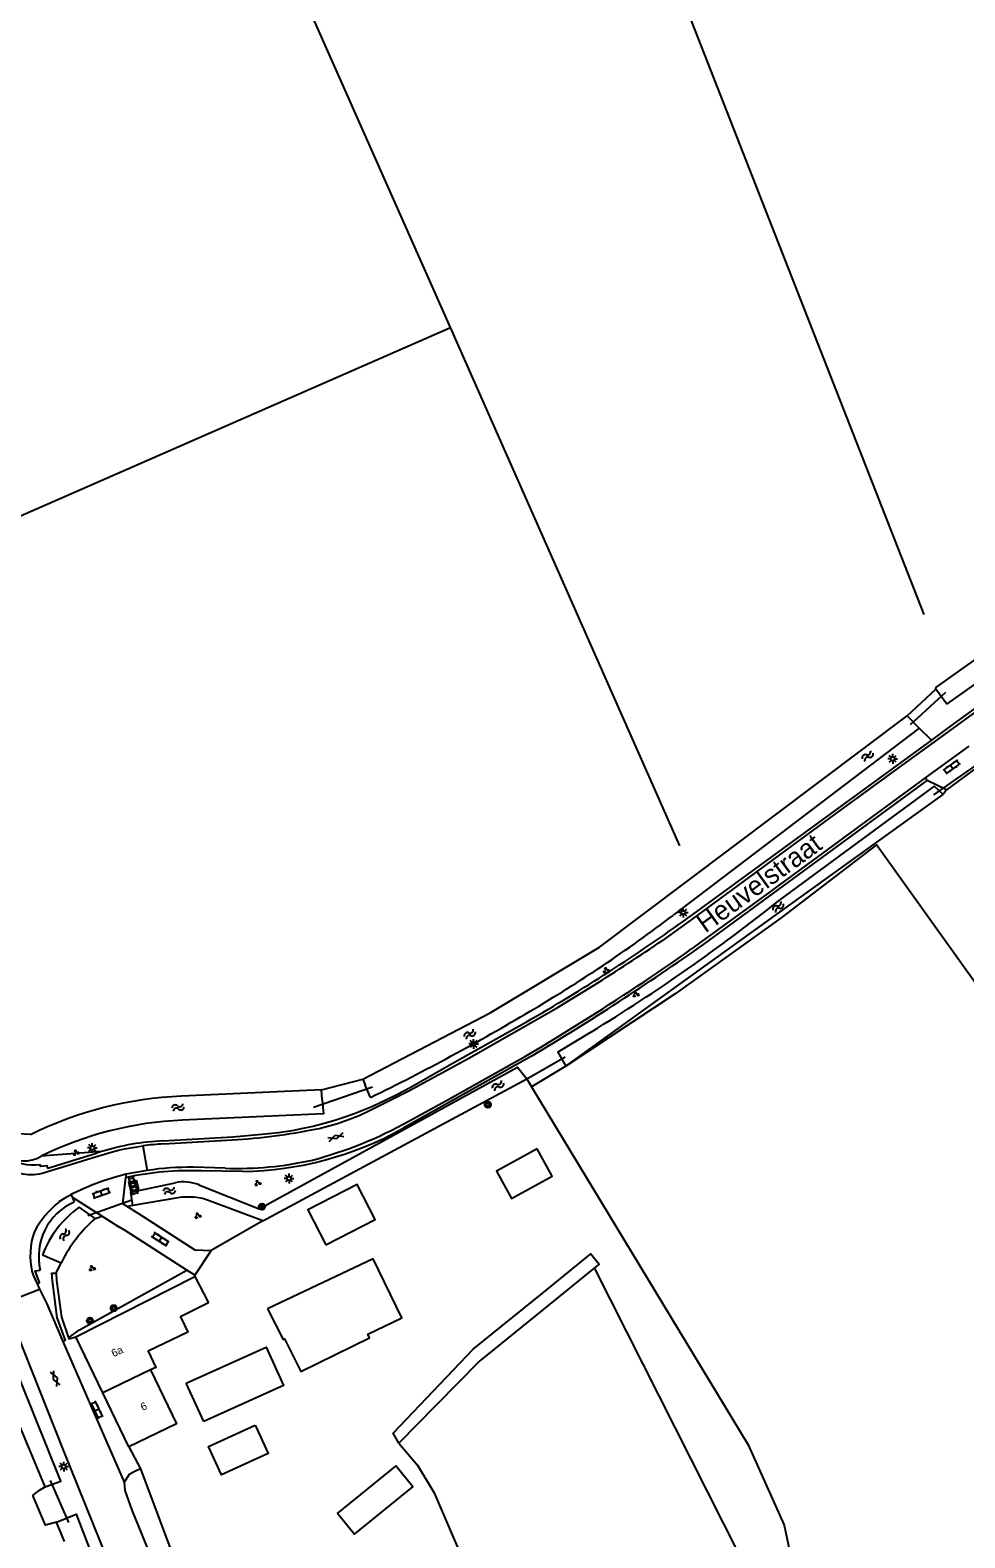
# Model space of a CAD drawing. Extents: x 136000 to 141000, y 400494 to 402006.
# Drawn here: x 137376.4 to 137496.6, y 400727.5 to 400921.3 of the extents above; entities that cross this region are included whole.
import ezdxf

# ---------------------------------------------------------------- set-up
doc = ezdxf.new("R2010")
doc.units = 0
for name, color, linetype in [('gg-afsc-draadraster', 7, 'Continuous'), ('gg-afsc-erfafscheiding', 7, 'Continuous'), ('gg-afsc-lijn draadraster', 7, 'Continuous'), ('gg-anno-huisnummerreeks BGT', 7, 'Continuous'), ('gg-anno-openbare ruimte label', 7, 'Continuous'), ('gg-bbg-bijgebouw', 7, 'Continuous'), ('gg-bbg-gedigitaliseerde bijgebouw', 7, 'Continuous'), ('gg-bbg-hoofdgebouw', 7, 'Continuous'), ('gg-bbg-luifel en loopbrug', 7, 'Continuous'), ('gg-bbg-tussenscheiding', 7, 'Continuous'), ('gg-knt-bronhoudergrens', 7, 'Continuous'), ('gg-knt-verharding', 7, 'Continuous'), ('gg-kntw-bovenkant insteek waterloop', 7, 'Continuous'), ('gg-kntw-midden sloot', 7, 'Continuous'), ('gg-kwrk-duiker nz buis', 7, 'Continuous'), ('gt-grn-groengrens', 7, 'Continuous'), ('gt-symb-boom', 7, 'Continuous'), ('gt-symb-brandkraan', 7, 'Continuous'), ('gt-symb-gesloten verharding', 7, 'Continuous'), ('gt-symb-groenvak', 7, 'Continuous'), ('gt-symb-klinker verharding', 7, 'Continuous'), ('gt-symb-lichtmast', 7, 'Continuous'), ('gt-symb-watersymbool', 7, 'Continuous')]:
    doc.layers.add(name, color=color, linetype=linetype)

# ---------------------------------------------------------------- blocks, each defined once
blk = doc.blocks.new('gt0-WA')
at = {"layer": 'gt-symb-watersymbool'}
for centre, start, end in [((-0.32, 0.02), 28.0725, 151.9275), ((0.43, 0.42), 208.0725, 331.9275), ((-0.32, -0.43), 28.0725, 151.9275), ((0.43, -0.03), 208.0725, 331.9275)]:
    blk.add_arc(centre, 0.425, start, end, dxfattribs=at)
blk = doc.blocks.new('gt0-LMAST')
at = {"layer": 'gt-symb-lichtmast'}
for p, q in [((-0.18, 0.17), (-0.45, 0.44)), ((-0.01, 0.25), (-0.01, 0.62)), ((0.17, 0.17), (0.44, 0.44)), ((-0.26, 0), (-0.63, 0)), ((-0.18, -0.18), (-0.45, -0.45)), ((-0.01, -0.25), (-0.01, -0.63)), ((0.44, -0.45), (0.17, -0.18)), ((0.24, 0), (0.62, 0))]:
    blk.add_line(p, q, dxfattribs=at)
blk.add_circle((-0.01, 0), 0.25, dxfattribs=at)
blk = doc.blocks.new('gt0-KL1')
at = {"layer": 'gt-symb-klinker verharding'}
for p, q in [((-1.15, 0.3), (1.15, 0.3)), ((-1, -0.3), (-1, 0.3)), ((-0.5, 0.3), (-0.5, 0.45)), ((0, -0.3), (0, 0.3)), ((0.5, 0.3), (0.5, 0.45)), ((1, -0.3), (1, 0.3)), ((-1.15, -0.3), (1.15, -0.3)), ((-0.5, -0.45), (-0.5, -0.3)), ((0.5, -0.45), (0.5, -0.3))]:
    blk.add_line(p, q, dxfattribs=at)
blk = doc.blocks.new('gt0-BOOM')
at = {"layer": 'gt-symb-boom'}
for radius in [0.4, 0.2]:
    blk.add_circle((0, 0), radius, dxfattribs=at)
blk = doc.blocks.new('gt0-GRVAK')
at = {"layer": 'gt-symb-groenvak'}
for p, q in [((-0.11, 0.19), (-0.23, 0.24)), ((-0.18, 0.15), (0.09, 0.15)), ((-0.09, 0.21), (-0.16, 0.32)), ((-0.05, 0.21), (-0.05, 0.39)), ((0, 0.21), (0.06, 0.32)), ((0.02, 0.19), (0.13, 0.24)), ((0.26, -0.05), (0.2, 0.06)), ((0.3, -0.05), (0.3, 0.13)), ((0.35, -0.05), (0.41, 0.06)), ((-0.24, -0.23), (-0.36, -0.18)), ((-0.32, -0.26), (-0.05, -0.26)), ((-0.23, -0.21), (-0.29, -0.09)), ((-0.18, -0.2), (-0.18, -0.02)), ((-0.14, -0.21), (-0.07, -0.09)), ((-0.12, -0.23), (0, -0.18)), ((0.24, -0.07), (0.12, -0.02)), ((0.17, -0.11), (0.44, -0.11)), ((0.37, -0.07), (0.49, -0.02))]:
    blk.add_line(p, q, dxfattribs=at)
blk = doc.blocks.new('gt0-BR')
at = {"layer": 'gt-symb-brandkraan'}
for centre, radius, start, end in [((-0.24, 0), 0.206, 107.5669, 252.4331), ((0.6, -2.66), 3, 106.892, 107.5669), ((0, -0.69), 0.938, 73.108, 106.892), ((-0.6, -2.66), 3, 72.4331, 73.108), ((0.24, 0), 0.206, 287.567, 72.4331), ((0.6, 2.66), 3, 252.4331, 253.108), ((0, 0.69), 0.938, 253.108, 286.8921), ((-0.6, 2.66), 3, 286.8921, 287.567)]:
    blk.add_arc(centre, radius, start, end, dxfattribs=at)
blk = doc.blocks.new('gt0-GESVH1')
at = {"layer": 'gt-symb-gesloten verharding'}
for p, q in [((-0.99, -0.26), (0.01, 0.24)), ((0.01, -0.26), (-0.99, 0.24)), ((0.01, 0.24), (1.01, -0.26)), ((1.01, 0.24), (0.01, -0.26))]:
    blk.add_line(p, q, dxfattribs=at)

msp = doc.modelspace()

# ---------------------------------------------------------------- linework, layer by layer
at = {"layer": 'gg-afsc-draadraster'}
msp.add_line((137445.3, 400788.16), (137440.89, 400785.49), dxfattribs=at)
for points in [[(137574.82, 400766.45), (137564.03, 400780.91), (137556.53, 400775.22), (137550.61, 400770.86), (137540.84, 400784.86), (137518.92, 400769.04), (137502.17, 400792.96), (137485.23, 400816.63), (137472.97, 400807.22), (137459.36, 400797.46), (137445.3, 400788.16)], [(137428.37, 400733.35), (137439.78, 400706.75), (137440.85, 400707.2), (137445.39, 400696.61), (137443.56, 400695.83)]]:
    msp.add_lwpolyline(points, dxfattribs=at)
at = {"layer": 'gg-afsc-erfafscheiding'}
for p, q in [((137489.19, 400833.19), (137492.87, 400836.61)), ((137406.34, 400768.29), (137399.71, 400764.48))]:
    msp.add_line(p, q, dxfattribs=at)
msp.add_lwpolyline([(137379.82, 400729.57), (137378.4, 400729.17), (137376.77, 400733), (137377.62, 400733.67), (137378.34, 400734.09)], dxfattribs=at)
at = {"layer": 'gg-afsc-lijn draadraster'}
msp.add_line((137445.3, 400788.16), (137440.89, 400785.49), dxfattribs=at)
msp.add_lwpolyline([(137574.82, 400766.45), (137564.03, 400780.91), (137556.53, 400775.22), (137550.61, 400770.86), (137540.84, 400784.86), (137518.92, 400769.04), (137502.17, 400792.96), (137485.23, 400816.63), (137472.97, 400807.22), (137459.36, 400797.46), (137445.3, 400788.16)], dxfattribs=at)
at = {"layer": 'gg-bbg-bijgebouw'}
msp.add_line((137398.75, 400742.5), (137396.5, 400747.41), dxfattribs=at)
for points in [[(137406.95, 400756.99), (137408.95, 400753.02), (137409.14, 400753.11), (137411.21, 400748.94), (137420.05, 400753.25), (137419.83, 400753.71), (137424.2, 400755.83), (137420.51, 400763.4), (137406.95, 400756.99)], [(137396.5, 400747.41), (137406.75, 400752.05), (137408.98, 400747.13), (137398.75, 400742.5)], [(137405.37, 400742.02), (137407.03, 400738.38), (137401.01, 400735.63), (137399.35, 400739.28), (137405.37, 400742.02)]]:
    msp.add_lwpolyline(points, dxfattribs=at)
at = {"layer": 'gg-bbg-gedigitaliseerde bijgebouw'}
for points in [[(137441.6, 400777.52), (137436.38, 400774.66), (137438.3, 400771.16), (137443.52, 400774.03), (137441.6, 400777.52)], [(137423.43, 400736.8), (137415.93, 400730.72), (137418.13, 400728), (137425.63, 400734.09), (137423.43, 400736.8)]]:
    msp.add_lwpolyline(points, dxfattribs=at)
at = {"layer": 'gg-bbg-hoofdgebouw'}
for p, q in [((137382.3, 400753.4), (137397.62, 400761.14)), ((137397.62, 400761.14), (137399.34, 400757.73)), ((137385.77, 400746.18), (137382.3, 400753.4)), ((137389.11, 400739.25), (137385.77, 400746.18))]:
    msp.add_line(p, q, dxfattribs=at)
for points in [[(137399.34, 400757.73), (137395.76, 400755.95), (137396.7, 400754), (137391.58, 400751.54), (137392.58, 400749.45), (137391.9, 400749.13)], [(137391.9, 400749.13), (137395.24, 400742.2), (137389.11, 400739.25)]]:
    msp.add_lwpolyline(points, dxfattribs=at)
at = {"layer": 'gg-bbg-luifel en loopbrug'}
msp.add_lwpolyline([(137414.45, 400765.19), (137420.78, 400768.45), (137418.46, 400772.95), (137412.13, 400769.7), (137414.45, 400765.19)], dxfattribs=at)
at = {"layer": 'gg-bbg-tussenscheiding'}
msp.add_line((137391.9, 400749.13), (137385.77, 400746.18), dxfattribs=at)
at = {"layer": 'gg-knt-bronhoudergrens'}
for points in [[(137440.89, 400785.49), (137468.72, 400739.5), (137473.35, 400729.18), (137474.96, 400721.64), (137474.68, 400714.1), (137473.24, 400676.77)], [(137468.93, 400678.71), (137469.72, 400721.2), (137449, 400762.23)], [(137423.82, 400739.73), (137426.23, 400736.89), (137428.37, 400733.35)]]:
    msp.add_lwpolyline(points, dxfattribs=at)
at = {"layer": 'gg-knt-verharding'}
for p, q in [((137497.09, 400829.31), (137491.51, 400825.24)), ((137491.76, 400824.89), (137491.51, 400825.24)), ((137498.12, 400826.55), (137494.22, 400823.67)), ((137462.99, 400803.8), (137491.76, 400824.89)), ((137494.22, 400823.67), (137491.76, 400824.89)), ((137440.97, 400789.49), (137424.37, 400780.18)), ((137393.56, 400778.17), (137401.71, 400778.64)), ((137390.92, 400777.93), (137391.45, 400774.75)), ((137391.45, 400774.75), (137388.74, 400774.29)), ((137401.48, 400775.05), (137397.41, 400775.17)), ((137403.76, 400774.63), (137398.49, 400774.71)), ((137388.74, 400774.29), (137387.12, 400773.81)), ((137388.81, 400773.87), (137388.74, 400774.29)), ((137381.68, 400771.65), (137381.86, 400771.25)), ((137381.86, 400771.25), (137382.08, 400770.71)), ((137385.7, 400768.89), (137387.83, 400767.53)), ((137389.58, 400769.72), (137388.92, 400770.13)), ((137399.71, 400764.48), (137397.6, 400761.29)), ((137397.6, 400761.29), (137396.59, 400761.94)), ((137397.6, 400761.29), (137397.62, 400761.14)), ((137373.25, 400757.81), (137377.63, 400759.52)), ((137377.33, 400760.2), (137377.63, 400759.52)), ((137389.11, 400739.25), (137390.61, 400736.41)), ((137389.99, 400736.11), (137389.14, 400735.68)), ((137390.61, 400736.41), (137389.99, 400736.11)), ((137389.14, 400735.68), (137388.52, 400734.69))]:
    msp.add_line(p, q, dxfattribs=at)
for points in [[(137566.7, 400883.53), (137558.63, 400877.45), (137550.43, 400871.48), (137539.55, 400863.68), (137504.45, 400838.41), (137492.59, 400829.8)], [(137539.7, 400864.3), (137534.42, 400860.52), (137495.12, 400832.14), (137492.3, 400830.08)], [(137492.59, 400829.8), (137489.03, 400827.22), (137479.88, 400820.53), (137461.6, 400807.11), (137457.72, 400804.33)], [(137492.3, 400830.08), (137477.6, 400819.36), (137461.12, 400807.3)], [(137491.51, 400825.24), (137470.68, 400809.94), (137461.46, 400803.23)], [(137420.07, 400782.45), (137425.13, 400784.99), (137432.83, 400789.21), (137444.1, 400795.63), (137448.86, 400798.53)], [(137393.47, 400778.56), (137402.5, 400779.1), (137406.21, 400779.42), (137408.34, 400779.66), (137410.38, 400779.96), (137411.3, 400780.14), (137412.82, 400780.47), (137414.23, 400780.82), (137415.58, 400781.21), (137416.9, 400781.64), (137418.23, 400782.13), (137420.35, 400783), (137422.08, 400783.79), (137423.67, 400784.58), (137425.18, 400785.39), (137430.61, 400788.47), (137440.31, 400793.91)], [(137425.03, 400781.06), (137430.32, 400783.96), (137440.11, 400789.46), (137442.16, 400790.67), (137444.19, 400791.91), (137447.34, 400793.86)], [(137384.55, 400776.83), (137378.71, 400775), (137378.6, 400775.36), (137377.77, 400775.26), (137377.74, 400775.51)], [(137377.99, 400774.42), (137384.83, 400776.53), (137386.83, 400777.12), (137387.8, 400777.36)], [(137387.8, 400777.36), (137388.57, 400777.55), (137390.92, 400777.93)], [(137388.92, 400770.13), (137388.35, 400770.48), (137388.72, 400773.84), (137388.81, 400773.87)], [(137390.05, 400773.51), (137390.34, 400772.35), (137389.4, 400772.1), (137389.1, 400773.25), (137390.05, 400773.51)], [(137381.68, 400771.65), (137381.08, 400771.34), (137380.12, 400770.71)], [(137381.86, 400771.25), (137381.93, 400771.29), (137385.7, 400768.89)], [(137389.58, 400769.72), (137390.36, 400769.21), (137397.62, 400764.55), (137399.71, 400764.48)], [(137396.59, 400761.94), (137388.65, 400767.04), (137387.83, 400767.53)], [(137376.69, 400761.71), (137376.83, 400761.31), (137377.33, 400760.2)], [(137377.33, 400760.2), (137377.65, 400760.35), (137377.06, 400761.88), (137377.72, 400761.94)], [(137379.91, 400755.75), (137379.9, 400755.83), (137379.29, 400760.57), (137379.21, 400761.58), (137379.78, 400761.57)], [(137379.78, 400761.57), (137379.81, 400760.6), (137380.47, 400755.89), (137381.37, 400753.24)], [(137377.63, 400759.52), (137378.58, 400757.63), (137380.64, 400752.8)], [(137388.35, 400719.94), (137380.71, 400738.83), (137373.74, 400756.43)], [(137379.91, 400755.75), (137380.92, 400752.9), (137380.64, 400752.8)], [(137381.37, 400753.24), (137381.41, 400753.11), (137382.3, 400753.4)], [(137380.64, 400752.8), (137383.62, 400745.87), (137388.52, 400734.69)], [(137388.52, 400734.69), (137388.58, 400733.61), (137389.52, 400731.1), (137393.24, 400721.99)]]:
    msp.add_lwpolyline(points, dxfattribs=at)
for centre, radius, start, end in [((137324.79, 400996.23), 232.98, 299.7241, 305.8131), ((137258.79, 401093.77), 354.65, 300.9096, 305.154), ((137327.62, 400993.48), 229.57, 301.8771, 304.5224), ((137310.65, 401015.26), 260.19, 301.6918, 305.4239), ((137406.85, 400809.74), 30.32, 280.941, 295.8413), ((137399.17, 400827.42), 53.08, 284.7954, 299.157), ((137394.8, 400747.84), 30.75, 92.4754, 107.3664), ((137398.09, 400853.58), 75.02, 272.761, 281.1537), ((137403.05, 400818.31), 43.69, 270.9252, 299.2118), ((137376.92, 400781.6), 6.14, 232.9539, 277.6227), ((137394.47, 400748.79), 29.74, 107.3136, 109.4922), ((137395.7, 400739.97), 38.26, 93.2039, 97.1653), ((137376.57, 400779.9), 5.66, 225.638, 284.5973), ((137397.1, 400734.31), 40.42, 88.0266, 101.8394), ((137396.76, 400741.23), 33.94, 88.9129, 99.0026), ((137402.91, 400820.44), 45.42, 268.1941, 282.4769), ((137395.5, 400744.78), 30.22, 106.1018, 117.2249), ((137388.09, 400760.85), 12.67, 128.9611, 151.404), ((137385.18, 400763.7), 7.66, 113.8705, 193.2716), ((137385.66, 400763.84), 9.22, 160.5364, 193.3699)]:
    msp.add_arc(centre, radius, start, end, dxfattribs=at)
at = {"layer": 'gg-kntw-bovenkant insteek waterloop'}
for p, q in [((137494.29, 400834.68), (137513.1, 400848.04)), ((137492.76, 400836.78), (137492.87, 400836.61)), ((137494.29, 400834.68), (137492.87, 400836.61)), ((137489.19, 400833.19), (137490.72, 400831.59)), ((137490.72, 400831.59), (137459.09, 400807.55)), ((137445.3, 400788.16), (137493.82, 400823.1)), ((137406.34, 400768.29), (137440.26, 400786.52)), ((137419.18, 400786.49), (137419.5, 400785.74)), ((137413.88, 400785.11), (137395.89, 400784.32)), ((137413.98, 400783.82), (137413.88, 400785.11)), ((137420.19, 400784.15), (137419.5, 400785.74)), ((137376.46, 400779.37), (137374.21, 400779.53)), ((137395.42, 400771.23), (137389.62, 400770.24)), ((137406.34, 400768.29), (137399.59, 400770.83)), ((137384.79, 400768.58), (137382.72, 400770.05)), ((137378, 400763.91), (137380.43, 400762.88)), ((137378.34, 400734.09), (137371.23, 400751.18)), ((137380.86, 400727.09), (137379.82, 400729.57))]:
    msp.add_line(p, q, dxfattribs=at)
for points in [[(137553.66, 400880.12), (137553, 400879.7), (137511.59, 400850.16), (137492.76, 400836.78)], [(137419.18, 400786.49), (137435.58, 400795.01), (137449.63, 400803.44), (137489.19, 400833.19)], [(137493.82, 400823.1), (137492.65, 400824.16), (137472.7, 400809.46)], [(137448.58, 400792.59), (137444.26, 400789.97), (137445.3, 400788.16)], [(137398.13, 400772.91), (137405.85, 400769.83), (137439.1, 400788.05), (137440.26, 400786.52)], [(137413.98, 400783.82), (137414.12, 400782.02), (137395.99, 400781.22)], [(137389.62, 400770.24), (137389.38, 400771.99), (137395.09, 400773.18)], [(137423.82, 400739.73), (137423.1, 400741), (137433.39, 400751.81), (137442.25, 400758.97), (137448.52, 400764.04), (137449.6, 400762.71), (137449, 400762.23)], [(137449, 400762.23), (137442.35, 400756.85), (137434.26, 400750.3), (137428.58, 400744.55), (137423.82, 400739.73)], [(137378.34, 400734.09), (137380.38, 400734.82), (137373.5, 400751.88), (137371.23, 400751.18)], [(137379.82, 400729.57), (137382.34, 400730.59), (137386.54, 400719.65), (137384.32, 400718.85)]]:
    msp.add_lwpolyline(points, dxfattribs=at)
for centre, radius, start, end in [((137347.05, 400954.96), 185.16, 300.3863, 307.238), ((137329.22, 400988.93), 229.78, 301.2971, 308.6414), ((137301.38, 401028.45), 271.66, 295.9347, 300.8548), ((137397.98, 400735.52), 48.84, 92.4577, 116.1484), ((137397.98, 400735.55), 45.72, 92.4905, 116.157), ((137375.61, 400780.34), 4.36, 236.7088, 300.5047), ((137396.17, 400767.97), 5.32, 68.3137, 101.6882), ((137396.76, 400763.31), 8.04, 69.3799, 99.6528), ((137390.68, 400759.04), 13.58, 125.8807, 159.0028), ((137397.06, 400754.69), 18.54, 131.4474, 153.7583)]:
    msp.add_arc(centre, radius, start, end, dxfattribs=at)
at = {"layer": 'gg-kntw-midden sloot'}
for p, q in [((137453.63, 400942.33), (137491.3, 400846.23)), ((137430.45, 400883.09), (137412.36, 400923.94)), ((137352.88, 400849.12), (137430.45, 400883.09)), ((137459.94, 400816.49), (137430.45, 400883.09))]:
    msp.add_line(p, q, dxfattribs=at)
at = {"layer": 'gg-kwrk-duiker nz buis'}
for p, q in [((137494.11, 400836.19), (137489.55, 400832.02)), ((137492.62, 400823.02), (137499.9, 400828.14)), ((137440.26, 400786.52), (137445.23, 400789.36)), ((137420.46, 400785.48), (137412.84, 400782.84)), ((137389.52, 400770.96), (137383.83, 400768.93)), ((137381.4, 400729.52), (137379.04, 400734.92))]:
    msp.add_line(p, q, dxfattribs=at)
at = {"layer": 'gt-grn-groengrens'}
for p, q in [((137492.3, 400830.08), (137490.72, 400831.59)), ((137494.22, 400823.67), (137493.82, 400823.1)), ((137413.88, 400785.11), (137419.18, 400786.49)), ((137440.26, 400786.52), (137440.89, 400785.49)), ((137385.62, 400777.19), (137377.82, 400776.58)), ((137384.79, 400768.58), (137385.7, 400768.89)), ((137389.62, 400770.24), (137388.92, 400770.13)), ((137379.78, 400761.57), (137380.43, 400762.88)), ((137390.61, 400736.41), (137403.58, 400701.83))]:
    msp.add_line(p, q, dxfattribs=at)
msp.add_lwpolyline([(137381.37, 400753.24), (137382.78, 400754.28), (137396.59, 400761.94)], dxfattribs=at)

# ---------------------------------------------------------------- block references
at = {"layer": 'gt-symb-boom'}
for p in [(137435.27, 400783.21), (137406.24, 400770.12), (137387.18, 400757.06), (137384.11, 400755.45)]:
    msp.add_blockref('gt0-BOOM', p, dxfattribs=at)
at = {"layer": 'gt-symb-brandkraan', "rotation": 11.073871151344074}
msp.add_blockref('gt0-BR', (137389.74, 400772.89), dxfattribs=at)
at = {"layer": 'gt-symb-gesloten verharding'}
for p, rotation in [((137415.73, 400779.05), 18.90606100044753), ((137379.66, 400748.03), -65.92116276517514)]:
    msp.add_blockref('gt0-GESVH1', p, dxfattribs=dict(at, rotation=rotation))
at = {"layer": 'gt-symb-groenvak'}
for p in [(137450.47, 400800.49), (137454.28, 400797.4), (137382.3, 400777.05), (137405.66, 400773.14), (137397.97, 400768.95), (137384.38, 400762.19)]:
    msp.add_blockref('gt0-GRVAK', p, dxfattribs=at)
at = {"layer": 'gt-symb-klinker verharding'}
for p, rotation in [((137494.9, 400826.64), -144.35579985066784), ((137389.66, 400772.79), -74.44827510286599), ((137385.57, 400771.86), 19.033079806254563), ((137393.17, 400765.91), 147.8671041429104), ((137384.98, 400744), -64.5883992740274)]:
    msp.add_blockref('gt0-KL1', p, dxfattribs=dict(at, rotation=rotation))
at = {"layer": 'gt-symb-lichtmast'}
for p in [(137487.33, 400827.67), (137460.39, 400807.91), (137433.44, 400791.02), (137384.43, 400777.66), (137409.72, 400773.73), (137380.75, 400736.71)]:
    msp.add_blockref('gt0-LMAST', p, dxfattribs=at)
at = {"layer": 'gt-symb-watersymbool'}
for p, rotation in [((137484.14, 400828.06), -135.64829798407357), ((137472.64, 400808.65), -132.6089961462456), ((137432.99, 400792.3), -140.6420430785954), ((137436.62, 400785.69), -140.6420430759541), ((137395.49, 400782.87), -160.67751762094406), ((137394.38, 400772.15), -160.67751762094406), ((137380.9, 400766.55), -115.6430708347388)]:
    msp.add_blockref('gt0-WA', p, dxfattribs=dict(at, rotation=rotation))

# ---------------------------------------------------------------- texts
at = {"layer": 'gg-anno-huisnummerreeks BGT'}
for s, p in [('6a', (137387.16, 400750.74)), ('6', (137390.91, 400743.83))]:
    msp.add_text(s, height=1, rotation=25.7, dxfattribs=at).set_placement(p)
at = {"layer": 'gg-anno-openbare ruimte label'}
msp.add_text('Heuvelstraat', height=2.5, rotation=35.9, dxfattribs=at).set_placement((137463.24, 400805.2))

doc.saveas('drawing.dxf')
